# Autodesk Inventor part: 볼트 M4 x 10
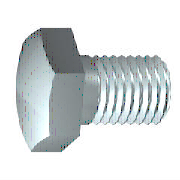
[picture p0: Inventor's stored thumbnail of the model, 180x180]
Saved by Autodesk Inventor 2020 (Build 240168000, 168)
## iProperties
Created: 2012-02
Part Number: 볼트 M4 x 10
Material: 스테인리스강
Description: 6각 머리 나사
Document SubType Name: Modeling
Standard: ISO 4017
Designer: mduedu
Standard Revision: Third edition 1999-08-15
Standards Organization: ISO
Language: ko-KR
Size Designation: M4 x 10
Categories: <MemberInstance><Categories><Category DisplayName="조임쇠" InternalName="e4da775c-781d-43d5-af7c-5136215cf5a6" Mnemonic="FSTN"><Category DisplayName="볼트" InternalN
Density: 8.08 g/cm^3
Appearance: 기본값
IsCustomPart: 0
Author: mduedu
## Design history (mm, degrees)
sketch "스케치1"
  geometry: L1 (0, 3.015)-(0, 2); L2 (2.1, 2)-(10, 2); L3 (10, 2)-(10, 0); L4 (10, 0)-(-0.4, 0); L5 (-2.48, 0)-(12.08, 0) reference; L6 (-0.4, 0)-(-0.4, 3.015); L7 (-0.4, 3.015)-(0, 3.015); L8 (2.1, 2)-(1.67, 2); L9 (1.67, 2)-(0, 2); L10 (0, -0.603)-(0, 3.618) reference
  constraints: 16 end point, 2 collinear, 2 perpendicular, 1 parallel
  dimensions: "d0" = 10 distance between parallel lines of L3 L1 (= NLG); "d1" = 7.9 distance from line of L2.start L3 (= GEL); "d2" = 4 diameter of L2 L4 (= GD); "d9" = 0.4001 distance between parallel lines of L6 L1 (computed from SD); "d10" = 6.03 diameter of L7 L4 (= SD2); "d13" = 0.42952 distance of L2.start L8.end (computed from GAL); "d14" = 4 diameter of L9 L4 (= BDM)
revolve "본체" sketch "스케치1" stored, may be unused: angle "d12" = 90 deg
sketch "스케치2"
  geometry: L1 (0, 4.041)-(3.5, 2.021); L2 (3.5, 2.021)-(3.5, -2.021); L3 (3.5, -2.021)-(0, -4.041); L4 (0, -4.041)-(-3.5, -2.021); L5 (-3.5, -2.021)-(-3.5, 2.021); L6 (-3.5, 2.021)-(0, 4.041); 2 further points
  constraints: 12 end point, 1 coincident, 1 vertical, 11 other
  dimensions: "d11" = 7 distance between parallel lines of L5 L2 (= SW)
extrude "머리" join sketch "스케치2" distance "d3" = 2.4 (= KOH - SD); taper "d4" = 0 deg
sketch "스케치4"
  geometry: L1 (-2.8, 3.5)-(-2.8, 4.041); L2 (-2.8, 4.041)-(-2.487, 4.041); L3 (-2.487, 4.041)-(-2.8, 3.5); L4 (-3.28, 0)-(0.08, 0) reference; L5 (-0.4, 4.041)-(-2.8, 4.041) reference; L6 (-2.8, 2.021)-(-2.8, 4.041) reference
  constraints: 6 end point, 2 collinear, 1 perpendicular, 1 vertical
  dimensions: "d5" = 30 deg angle of L3 L1 (= ANG1); "d19" = 7 diameter of L1.start L4 (= SW0)
revolve "모따기1" sketch "스케치4" stored, may be unused: angle "d21" = 90 deg
workplane "Work Plane1"
body "Solid1"
feature "스레드" dims "d15" = 7.9 (= GEL), "d16" = 0
chamfer "모따기2" distance "d6" = 0.42941 (= -0.5 x SPD + 0.5 x GD); stored, may be unused: second distance "d7" = 0.42952 (computed from GUL), angle "d55" = 45 deg
other parameters: "NLG" = 10 [user parameter; used in 1 equation term], "GD" = 4 (= NND) [user parameter; used in 2 equation terms], "BDM" = 4 (= NND) [user parameter; used in 1 equation term], "KOH" = 2.8 [user parameter; used in 1 equation term], "GEL" = 7.9 [user parameter; used in 2 equation terms], "SW" = 7 [user parameter; used in 2 equation terms], "SW0" = 7 (= SW) [user parameter; used in 1 equation term], "SPD" = 3.14117 (= NND - 1.2269 x PTC) [user parameter; used in 1 equation term], "SD2" = 6.03 [user parameter; used in 2 equation terms], "SD" = 0.4 [user parameter; used in 2 equation terms], "ANG1" = 30 deg [user parameter; used in 1 equation term], "GAL" = 0.42941 (= 0.61345 x PTC) [user parameter; used in 1 equation term], "GUL" = 0.42941 (= 0.61345 x PTC) [user parameter; used in 1 equation term], "d8" = 0, "RR" = 0.2 [user parameter], "d57" = 0, "d58" = 0, "TPU" = 14.28571 (computed from PTC) [user parameter], "GD1" = 3.14117 (= THREADDIA - 1.2269 x PTC) [user parameter], "THREADDIA" = 4 [user parameter; used in 1 equation term], "SDH" = 6.03 (= SD2) [user parameter], "SDHG" = 2.1 [user parameter], "TOA" = 30 deg [user parameter], "PTC" = 0.7 [user parameter; used in 5 equation terms], "NND" = 4 [user parameter; used in 3 equation terms], "E0" = 8.085 [user parameter]
